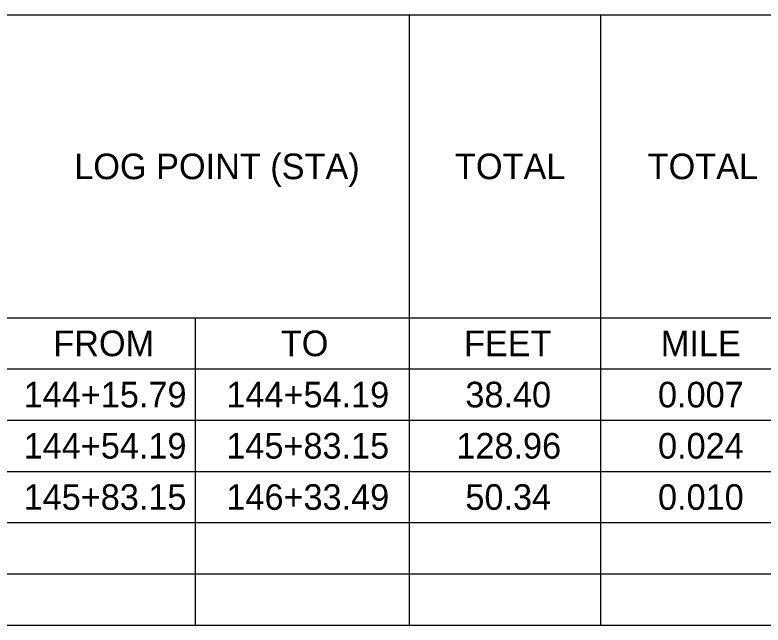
# Model space of a CAD drawing. Extents: x 0 to 34, y 0 to 22.
# Drawn here: x 4.377 to 8.407, y 3.513 to 6.801 of the extents above; entities that cross this region are included whole.
import ezdxf

# ---------------------------------------------------------------- set-up
doc = ezdxf.new("R2010")
doc.units = 0
doc.layers.add('SH_Text', color=7, linetype='Continuous')

msp = doc.modelspace()

# ---------------------------------------------------------------- linework, layer by layer
at = {"layer": 'SH_Text'}
for p, q in [((2.1442, 6.801), (5.3482, 6.801)), ((5.3482, 6.801), (7.5322, 6.801)), ((6.5002, 6.801), (6.5002, 5.997)), ((7.5322, 6.801), (8.5762, 6.801)), ((7.5322, 6.801), (7.5322, 5.997)), ((6.5002, 5.997), (6.5002, 5.169)), ((7.5322, 5.997), (7.5322, 5.169)), ((4.3162, 5.169), (5.3482, 5.169)), ((5.3482, 5.169), (7.5322, 5.169)), ((5.3482, 5.169), (5.3482, 4.065)), ((6.5002, 5.169), (6.5002, 4.065)), ((7.5322, 5.169), (8.5762, 5.169)), ((7.5322, 5.169), (7.5322, 4.065)), ((2.1442, 4.893), (5.3482, 4.893)), ((5.3482, 4.893), (7.5322, 4.893)), ((7.5322, 4.893), (8.5762, 4.893)), ((2.1442, 4.617), (5.3482, 4.617)), ((5.3482, 4.617), (7.5322, 4.617)), ((7.5322, 4.617), (8.5762, 4.617)), ((2.1442, 4.341), (5.3482, 4.341)), ((5.3482, 4.341), (7.5322, 4.341)), ((7.5322, 4.341), (8.5762, 4.341)), ((2.1442, 4.065), (5.3482, 4.065)), ((5.3482, 4.065), (7.5322, 4.065)), ((5.3482, 4.065), (5.3482, 3.789)), ((6.5002, 4.065), (6.5002, 3.789)), ((7.5322, 4.065), (8.5762, 4.065)), ((7.5322, 4.065), (7.5322, 3.789)), ((2.1442, 3.789), (5.3482, 3.789)), ((5.3482, 3.789), (7.5322, 3.789)), ((5.3482, 3.789), (5.3482, 3.513)), ((6.5002, 3.789), (6.5002, 3.513)), ((7.5322, 3.789), (8.5762, 3.789)), ((7.5322, 3.789), (7.5322, 3.513)), ((2.1442, 3.513), (5.3482, 3.513)), ((5.3482, 3.513), (7.5322, 3.513)), ((7.5322, 3.513), (8.5762, 3.513))]:
    msp.add_line(p, q, dxfattribs=at)

# ---------------------------------------------------------------- texts
for s, p in [('LOG POINT (STA)', (4.6962, 5.916)), ('TOTAL', (6.7476, 5.916)), ('TOTAL', (7.7856, 5.916)), ('FROM', (4.5832, 4.962)), ('TO', (5.8091, 4.962)), ('FEET', (6.7961, 4.962)), ('MILE', (7.8563, 4.962)), ('144+15.79', (4.4236, 4.686)), ('144+54.19', (5.5156, 4.686)), ('38.40', (6.8033, 4.686)), ('0.007', (7.8411, 4.686)), ('144+54.19', (4.4236, 4.41)), ('145+83.15', (5.5153, 4.41)), ('128.96', (6.7548, 4.41)), ('0.024', (7.8414, 4.41)), ('145+83.15', (4.4233, 4.134)), ('146+33.49', (5.5156, 4.134)), ('50.34', (6.8034, 4.134)), ('0.010', (7.8413, 4.134))]:
    msp.add_text(s, height=0.138, dxfattribs=at).set_placement(p)

doc.saveas('drawing.dxf')
